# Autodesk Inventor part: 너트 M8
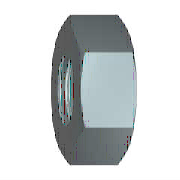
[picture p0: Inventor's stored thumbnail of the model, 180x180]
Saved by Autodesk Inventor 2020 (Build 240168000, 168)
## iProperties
Created: 2012-02
Part Number: 너트 M8
Material: 강철, 연강
Description: 6각 너트 및 6각 가는 너트
Document SubType Name: Modeling
Standard: KS B 1012
Designer: mduedu
Standards Organization: KS
Language: ko-KR
Size Designation: M 8
Categories: <MemberInstance><Categories><Category DisplayName="조임쇠" InternalName="e4da775c-781d-43d5-af7c-5136215cf5a6" Mnemonic="FSTN"><Category DisplayName="너트" InternalN
Density: 1 g/cm^3
Appearance: 강철
IsCustomPart: 1
Author: mduedu
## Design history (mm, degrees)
sketch "스케치1"
  geometry: L1 (-7.506, 0)-(-3.753, 6.5); L2 (-3.753, 6.5)-(3.753, 6.5); L3 (3.753, 6.5)-(7.506, 0); L4 (7.506, 0)-(3.753, -6.5); L5 (3.753, -6.5)-(-3.753, -6.5); L6 (-3.753, -6.5)-(-7.506, 0); 2 further points
  constraints: 12 end point, 1 coincident, 1 horizontal, 11 other
  dimensions: "d0" = 15.01111 distance of L3.end L1.start (= 1.1547 x SW)
extrude "본체" new body sketch "스케치1" distance "d1" = 5 (= KOH); taper "d2" = 0 deg
sketch "스케치2"
  geometry: L1 (0, 3.753)-(0, 7.506) reference; L2 (0, 7.506)-(5, 7.506) reference; L3 (5, 3.753)-(5, 7.506) reference; L4 (-1, 0)-(6, 0) reference; L5 (0.581, 7.506)-(0, 6.5); L6 (4.419, 7.506)-(5, 6.5)
  constraints: 4 end point, 4 point on line
  dimensions: "d3" = 30 deg angle of L1 L5 (= ANG1); "d4" = 30 deg angle of L3 L6 (= ANG2); "d5" = 13 diameter of L5.end L4 (= SW0); "d6" = 13 diameter of L6.end L4 (= SW01)
revolve "모따기1" sketch "스케치2" stored, may be unused: angle "d7" = 90 deg
sketch "스케치3"
  geometry: A1 r 6.5 centre (0, 0) between (-3.25, -5.629) and (3.25, -5.629) reference; 1 further point
  constraints: 1 coincident
hole "스레드" sketch "스케치3" at (0, 0) diameter "d25" = 6.647; stored, may be unused: countersink angle "d29" = 82 deg, drill point angle "d31" = 118 deg; dims "d26" = 6, "d27" = 4, "d28" = 2, "d30" = 8
workaxis "Work Axis1"
workplane "Work Plane1"
body "Solid1"
chamfer "모따기2" distance "d8" = 0.67658 (= -0.5 x GD1 + 0.5 x NND); stored, may be unused: angle "d9" = 30 deg, second distance "d40" = 0.67658 (= -0.5 x GD1 + 0.5 x NND)
chamfer "모따기3" distance "d10" = 0.67658 (= -0.5 x GD1 + 0.5 x NND); stored, may be unused: angle "d11" = 30 deg, second distance "d41" = 0.67658 (= -0.5 x GD1 + 0.5 x NND)
other parameters: "ANG1" = 30 deg [user parameter; used in 1 equation term], "ANG2" = 30 deg [user parameter; used in 1 equation term], "NND" = 8 [user parameter; used in 4 equation terms], "KOH" = 5 [user parameter; used in 1 equation term], "SW" = 13 [user parameter; used in 4 equation terms], "SW0" = 13 (= SW) [user parameter; used in 1 equation term], "SW01" = 13 (= SW) [user parameter; used in 1 equation term], "GD1" = 6.64684 (computed from THREADDIA, PTC, TOA) [user parameter; used in 4 equation terms], "d13" = 0, "d14" = 0, "d39" = 0, "d42" = 0, "GUL" = 0.67658 (= 0.541266 x PTC) [user parameter], "TPU" = 8 (computed from PTC) [user parameter], "THREADDIA" = 8 [user parameter; used in 1 equation term], "TOA" = 30 deg [user parameter; used in 1 equation term], "PTC" = 1.25 [user parameter; used in 4 equation terms], "E0" = 15.015 (= 1.155 x SW) [user parameter], "GAL" = 0.67658 (= 0.541266 x PTC) [user parameter]
